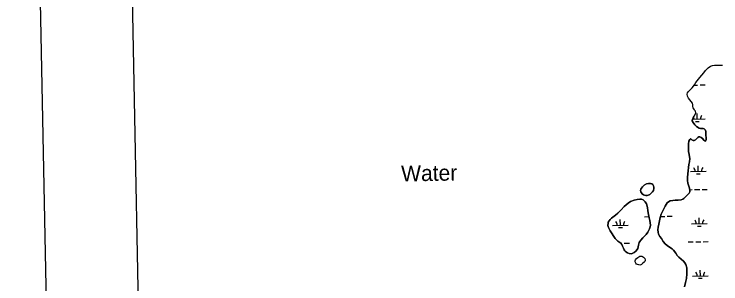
# Model space of a CAD drawing. Extents: x 3989314 to 4027622, y 243956 to 270014.
# Drawn here: x 3992659 to 3997154, y 258022 to 259739 of the extents above; entities that cross this region are included whole.
import ezdxf

# ---------------------------------------------------------------- set-up
doc = ezdxf.new("R2010")
doc.units = 0
for name, color, linetype in [('V-ANNO-SYMB', 7, 'Continuous'), ('V-GRID-FRAM', 7, 'Continuous'), ('V-RIVR-EDGE', 7, 'Continuous'), ('V-RIVR-IDEN', 7, 'Continuous'), ('V-WETL-SWMP', 7, 'Continuous')]:
    doc.layers.add(name, color=color, linetype=linetype)

msp = doc.modelspace()

# ---------------------------------------------------------------- linework, layer by layer
at = {"layer": 'V-ANNO-SYMB'}
msp.add_lwpolyline([(3993116.1, 245218.5), (4026192.7, 245877.7), (4025736.1, 268789.7), (3992659.5, 268130.6), (3993116.1, 245218.5)], dxfattribs=at)
at = {"layer": 'V-GRID-FRAM'}
msp.add_lwpolyline([(3993261.4, 267575.2), (4025156.8, 268210.8), (4025527.1, 250031.9), (3993615.7, 249396), (3993261.4, 267575.2)], dxfattribs=at)
at = {"layer": 'V-RIVR-EDGE'}
for points in [[(3996977.4, 259078.8), (3996984.3, 259088.8), (3996992.4, 259103.6), (3996994.4, 259111), (3996993.6, 259120.5), (3996989.7, 259126.5), (3996985.8, 259130.9), (3996978.6, 259142.5), (3996976.5, 259151.1), (3996975.6, 259161.5), (3996972.9, 259173.2), (3996957.5, 259192.7), (3996948.4, 259204.7), (3996942.3, 259216.8), (3996941, 259229), (3996942.4, 259237.6), (3996945.6, 259244.6), (3996951.7, 259251.7), (3996971, 259269.4), (3996986.1, 259288.9), (3996995.4, 259305), (3997019.8, 259336.4), (3997046.6, 259365.6), (3997057.4, 259380.3), (3997073.8, 259397.6), (3997087.9, 259407), (3997100.3, 259412), (3997114.6, 259414.7), (3997134, 259414.8), (3997150.8, 259413.4), (3997163.9, 259414.5)], [(3996977.4, 259078.8), (3996974, 259070.4), (3996972.8, 259060), (3996977.1, 259049.6), (3996989.2, 259033.9), (3996999.9, 259023.5), (3997016.9, 259013.4), (3997024.5, 259011.2), (3997033.7, 259010.6), (3997042.3, 259010.6), (3997048.4, 259008.6), (3997055.8, 259000.7), (3997058.9, 258989.7), (3997059.2, 258971.9), (3997060.1, 258947), (3997059.8, 258938.6), (3997057.9, 258933.7), (3997055.7, 258931.2), (3997052.8, 258931.6), (3997045.3, 258936.3), (3997036.8, 258947.1), (3997029.2, 258954.6), (3997021.1, 258958.7), (3997014.5, 258958.6), (3997008.4, 258953.7), (3997001.9, 258946.9), (3996992.7, 258937.9), (3996984.2, 258934), (3996977.6, 258934.6), (3996970.5, 258938.8), (3996963.3, 258944.9), (3996961, 258944.5), (3996957.2, 258941.4), (3996951.3, 258930.1), (3996949.1, 258913.4), (3996948.2, 258882.1), (3996948.5, 258865.6), (3996952.3, 258846), (3996955.6, 258831.5), (3996956.3, 258819.2), (3996954.5, 258799.4), (3996951.2, 258780.8), (3996943.2, 258721.9), (3996941.1, 258699.8), (3996941.6, 258681), (3996944.9, 258662.1), (3996950.7, 258643.7), (3996954.5, 258632.1), (3996957, 258616.6), (3996956.2, 258608.4), (3996952, 258599.6), (3996946.3, 258593), (3996935.7, 258583), (3996927.8, 258574.9), (3996919, 258566.3), (3996911.7, 258561.6), (3996901.3, 258557.5), (3996883.3, 258555.1), (3996862.9, 258554.6), (3996847.8, 258553.3), (3996831.6, 258550.2), (3996822.3, 258545.1), (3996813.3, 258537.5), (3996799.7, 258515.9), (3996787.6, 258491.6), (3996775.4, 258465.4), (3996769, 258445.1), (3996759, 258402.8), (3996754.9, 258383.6), (3996753.4, 258366.6), (3996754.7, 258350.9), (3996758.6, 258338), (3996765.4, 258323.9), (3996775.7, 258309.7), (3996788.3, 258291.8), (3996799.4, 258277.7), (3996813.3, 258266.3), (3996826.6, 258256.2), (3996843.6, 258244.4), (3996852.5, 258236.7), (3996867.3, 258216.9), (3996876.7, 258202.3), (3996887.8, 258191.1), (3996901.9, 258179.3), (3996917.3, 258165.7), (3996925.3, 258156.7), (3996930.9, 258145.3), (3996937.1, 258123.1), (3996938.3, 258102.6), (3996937.7, 258084.8), (3996935, 258056.8), (3996929.2, 258030.9), (3996922.8, 258003.7)], [(3996645.4, 258607.6), (3996649.1, 258600.9), (3996654.4, 258594.1), (3996662, 258589.1), (3996668.9, 258586.7), (3996677.1, 258585.1), (3996686.2, 258585.1), (3996692.6, 258586.6), (3996698.7, 258589.4), (3996701.9, 258591.5), (3996708.6, 258597.7), (3996719.2, 258608.7), (3996725.1, 258616.9), (3996727.9, 258628.7), (3996728, 258637.1), (3996726.6, 258645.8), (3996721, 258654.4), (3996716.1, 258658.8), (3996707.7, 258661.9), (3996694.7, 258661.6), (3996681.4, 258657.7), (3996667.2, 258649.5), (3996655.6, 258639.2), (3996648.5, 258631.6), (3996644.9, 258624.3), (3996643.3, 258616.9), (3996645.4, 258607.6)], [(3996439.2, 258381.1), (3996450.3, 258360), (3996462.5, 258339.9), (3996468.6, 258329.5), (3996481.8, 258310.2), (3996494, 258297), (3996498.7, 258294), (3996506.3, 258289.9), (3996512.5, 258285.7), (3996517.6, 258281.2), (3996523.5, 258273.1), (3996528.5, 258262.7), (3996534.4, 258248.2), (3996538.6, 258238.7), (3996544.5, 258231.6), (3996550.2, 258226.3), (3996559.6, 258220), (3996570.1, 258214.8), (3996582.9, 258213.6), (3996591.1, 258215.5), (3996602.2, 258221.4), (3996613.6, 258230.4), (3996622.5, 258239.9), (3996626.4, 258247.6), (3996629.8, 258267.2), (3996631.6, 258276.4), (3996634.8, 258284.8), (3996638.8, 258291.3), (3996645.5, 258300.9), (3996657.3, 258315.3), (3996665.8, 258323.2), (3996678.6, 258337), (3996689.7, 258351.5), (3996699.6, 258371.5), (3996704.5, 258385.8), (3996706.1, 258396.4), (3996705.2, 258411.5), (3996703.1, 258425.5), (3996699.1, 258442.9), (3996693.7, 258464.4), (3996689.7, 258486.4), (3996686.8, 258508.9), (3996680.6, 258530.7), (3996673, 258543.1), (3996667.4, 258550), (3996659.9, 258556.5), (3996648.6, 258560.3), (3996638.7, 258560.8), (3996622.8, 258559.1), (3996603.4, 258554.4), (3996580.4, 258545.3), (3996564.8, 258536.5), (3996551.1, 258525.8), (3996538.6, 258514.1), (3996521.1, 258494.1), (3996498, 258471.1), (3996484.8, 258460.3), (3996459.8, 258440.4), (3996449.8, 258430.7), (3996444.4, 258423.8), (3996437.7, 258414.6), (3996436.7, 258408.9), (3996435.7, 258393), (3996439.2, 258381.1)], [(3996611.8, 258175.2), (3996617.9, 258182.6), (3996627.1, 258189.9), (3996638.6, 258197.5), (3996644.5, 258198.4), (3996651.7, 258198.2), (3996656.8, 258196.2), (3996662.9, 258191.9), (3996668.2, 258186.4), (3996670.7, 258182.4), (3996673.2, 258175.7), (3996672.8, 258170.2), (3996670.8, 258165.1), (3996665.9, 258159.5), (3996656.2, 258151.1), (3996649.9, 258144.2), (3996645, 258142.7), (3996638.7, 258141.5), (3996631.9, 258142.2), (3996624.4, 258144.9), (3996618.7, 258147.7), (3996613.6, 258153.2), (3996610.3, 258161.1), (3996610, 258168.9), (3996611.8, 258175.2)]]:
    msp.add_lwpolyline(points, dxfattribs=at)
at = {"layer": 'V-WETL-SWMP'}
for p, q in [((3997057.4, 259380.3), (3997073.8, 259397.6)), ((3997073.8, 259397.6), (3997087.9, 259407)), ((3997087.9, 259407), (3997100.3, 259412)), ((3997100.3, 259412), (3997114.6, 259414.7)), ((3997114.6, 259414.7), (3997134, 259414.8)), ((3997134, 259414.8), (3997150.8, 259413.4)), ((3997150.8, 259413.4), (3997163.9, 259414.5)), ((3997019.8, 259336.4), (3997046.6, 259365.6)), ((3997046.6, 259365.6), (3997057.4, 259380.3)), ((3996995.4, 259305), (3997019.8, 259336.4)), ((3996951.7, 259251.7), (3996971, 259269.4)), ((3996971, 259269.4), (3996986.1, 259288.9)), ((3996985.1, 259287.5), (3997006.2, 259288)), ((3996986.1, 259288.9), (3996995.4, 259305)), ((3997022.2, 259288.3), (3997054.2, 259288.9)), ((3996941, 259229), (3996942.4, 259237.6)), ((3996942.3, 259216.8), (3996941, 259229)), ((3996948.4, 259204.7), (3996942.3, 259216.8)), ((3996942.4, 259237.6), (3996945.6, 259244.6)), ((3996945.6, 259244.6), (3996951.7, 259251.7)), ((3996957.5, 259192.7), (3996948.4, 259204.7)), ((3996972.9, 259173.2), (3996957.5, 259192.7)), ((3996975.6, 259161.5), (3996972.9, 259173.2)), ((3996976.5, 259151.1), (3996975.6, 259161.5)), ((3996978.6, 259142.5), (3996976.5, 259151.1)), ((3996985.8, 259130.9), (3996978.6, 259142.5)), ((3996989.7, 259126.5), (3996985.8, 259130.9)), ((3996993.6, 259120.5), (3996989.7, 259126.5)), ((3996977.4, 259078.8), (3996984.3, 259088.8)), ((3996984.3, 259088.8), (3996992.4, 259103.6)), ((3996992.4, 259103.6), (3996994.4, 259111)), ((3996994.4, 259111), (3996993.6, 259120.5)), ((3997004, 259070.6), (3997003.3, 259106.6)), ((3996972.8, 259060), (3996974, 259070.4)), ((3996977.1, 259049.6), (3996972.8, 259060)), ((3996974, 259070.4), (3996977.4, 259078.8)), ((3996974, 259070), (3997054, 259071.6)), ((3996989.2, 259033.9), (3996977.1, 259049.6)), ((3996992.3, 259055), (3997016.3, 259055.4)), ((3996999.9, 259023.5), (3996989.2, 259033.9)), ((3997016.9, 259013.4), (3996999.9, 259023.5)), ((3997024.5, 259011.2), (3997016.9, 259013.4)), ((3997033.7, 259010.6), (3997024.5, 259011.2)), ((3997042.3, 259010.6), (3997033.7, 259010.6)), ((3997048.4, 259008.6), (3997042.3, 259010.6)), ((3997055.8, 259000.7), (3997048.4, 259008.6)), ((3997058.9, 258989.7), (3997055.8, 259000.7)), ((3996992.7, 258937.9), (3997001.9, 258946.9)), ((3997001.9, 258946.9), (3997008.4, 258953.7)), ((3997008.4, 258953.7), (3997014.5, 258958.6)), ((3997010.4, 258955.3), (3997012.9, 258955.4)), ((3997014.5, 258958.6), (3997021.1, 258958.7)), ((3997021.1, 258958.7), (3997029.2, 258954.6)), ((3997029.2, 258954.6), (3997036.8, 258947.1)), ((3997036.8, 258947.1), (3997045.3, 258936.3)), ((3997059.2, 258971.9), (3997058.9, 258989.7)), ((3997060.1, 258947), (3997059.2, 258971.9)), ((3997059.7, 258956.3), (3997060.9, 258956.3)), ((3997059.8, 258938.6), (3997060.1, 258947)), ((3996948.2, 258882.1), (3996949.1, 258913.4)), ((3996949.1, 258913.4), (3996951.3, 258930.1)), ((3996951.3, 258930.1), (3996957.2, 258941.4)), ((3996957.2, 258941.4), (3996961, 258944.5)), ((3996961, 258944.5), (3996963.3, 258944.9)), ((3996963.3, 258944.9), (3996970.5, 258938.8)), ((3996970.5, 258938.8), (3996977.6, 258934.6)), ((3996977.6, 258934.6), (3996984.2, 258934)), ((3996984.2, 258934), (3996992.7, 258937.9)), ((3997045.3, 258936.3), (3997052.8, 258931.6)), ((3997052.8, 258931.6), (3997055.7, 258931.2)), ((3997055.7, 258931.2), (3997057.9, 258933.7)), ((3997057.9, 258933.7), (3997059.8, 258938.6)), ((3996948.5, 258865.6), (3996948.2, 258882.1)), ((3996952.3, 258846), (3996948.5, 258865.6)), ((3996955.6, 258831.5), (3996952.3, 258846)), ((3996954.5, 258799.4), (3996956.3, 258819.2)), ((3996956.3, 258819.2), (3996955.6, 258831.5)), ((3996943.2, 258721.9), (3996951.2, 258780.8)), ((3996951.2, 258780.8), (3996954.5, 258799.4)), ((3997010.6, 258738), (3997009.9, 258774)), ((3996941.1, 258699.8), (3996943.2, 258721.9)), ((3996960.6, 258737), (3997060.6, 258739)), ((3996998.9, 258722.4), (3997022.9, 258722.8)), ((3996941.6, 258681), (3996941.1, 258699.8)), ((3996944.9, 258662.1), (3996941.6, 258681)), ((3996950.7, 258643.7), (3996944.9, 258662.1)), ((3996954.5, 258632.1), (3996950.7, 258643.7)), ((3996957, 258616.6), (3996954.5, 258632.1)), ((3996935.7, 258583), (3996946.3, 258593)), ((3996946.3, 258593), (3996952, 258599.6)), ((3996952, 258599.6), (3996956.2, 258608.4)), ((3996956.2, 258621.5), (3996971.5, 258621.8)), ((3996956.2, 258608.4), (3996957, 258616.6)), ((3996987.5, 258622.1), (3997019.5, 258622.7)), ((3997035.5, 258623.1), (3997067.5, 258623.7)), ((3996813.3, 258537.5), (3996822.3, 258545.1)), ((3996822.3, 258545.1), (3996831.6, 258550.2)), ((3996831.6, 258550.2), (3996847.8, 258553.3)), ((3996847.8, 258553.3), (3996862.9, 258554.6)), ((3996862.9, 258554.6), (3996883.3, 258555.1)), ((3996883.3, 258555.1), (3996901.3, 258557.5)), ((3996901.3, 258557.5), (3996911.7, 258561.6)), ((3996911.7, 258561.6), (3996919, 258566.3)), ((3996919, 258566.3), (3996927.8, 258574.9)), ((3996927.8, 258574.9), (3996935.7, 258583)), ((3996787.6, 258491.6), (3996799.7, 258515.9)), ((3996799.7, 258515.9), (3996813.3, 258537.5)), ((3996769, 258445.1), (3996775.4, 258465.4)), ((3996775.4, 258465.4), (3996787.6, 258491.6)), ((3996813, 258452.1), (3996844.9, 258452.7)), ((3996515.4, 258395.4), (3996514.7, 258431.4)), ((3996669, 258449.2), (3996697.4, 258449.8)), ((3996759, 258402.8), (3996769, 258445.1)), ((3996770.9, 258451.3), (3996797, 258451.8)), ((3997017.2, 258405.4), (3997016.5, 258441.4)), ((3996465.4, 258394.4), (3996565.4, 258396.4)), ((3996503.7, 258379.7), (3996527.7, 258380.2)), ((3996753.4, 258366.6), (3996754.9, 258383.6)), ((3996754.7, 258350.9), (3996753.4, 258366.6)), ((3996754.9, 258383.6), (3996759, 258402.8)), ((3996967.3, 258404.4), (3997067.2, 258406.4)), ((3997005.6, 258389.7), (3997029.5, 258390.2)), ((3996758.6, 258338), (3996754.7, 258350.9)), ((3996765.4, 258323.9), (3996758.6, 258338)), ((3996775.7, 258309.7), (3996765.4, 258323.9)), ((3996518.5, 258280), (3996524.3, 258280.1)), ((3996540.3, 258280.5), (3996572.3, 258281.1)), ((3996788.3, 258291.8), (3996775.7, 258309.7)), ((3996799.4, 258277.7), (3996788.3, 258291.8)), ((3996813.3, 258266.3), (3996799.4, 258277.7)), ((3996946.1, 258288.5), (3996978.1, 258289.2)), ((3996994.1, 258289.5), (3997026.1, 258290.1)), ((3997042.1, 258290.5), (3997074.1, 258291.1)), ((3996826.6, 258256.2), (3996813.3, 258266.3)), ((3996843.6, 258244.4), (3996826.6, 258256.2)), ((3996852.5, 258236.7), (3996843.6, 258244.4)), ((3996867.3, 258216.9), (3996852.5, 258236.7)), ((3996876.7, 258202.3), (3996867.3, 258216.9)), ((3996887.8, 258191.1), (3996876.7, 258202.3)), ((3996901.9, 258179.3), (3996887.8, 258191.1)), ((3996917.3, 258165.7), (3996901.9, 258179.3)), ((3996925.3, 258156.7), (3996917.3, 258165.7)), ((3996930.9, 258145.3), (3996925.3, 258156.7)), ((3996937.1, 258123.1), (3996930.9, 258145.3)), ((3996938.3, 258102.6), (3996937.1, 258123.1)), ((3996937.7, 258084.8), (3996938.3, 258102.6)), ((3997023.9, 258072.8), (3997023.2, 258108.8)), ((3996929.2, 258030.9), (3996935, 258056.8)), ((3996935, 258056.8), (3996937.7, 258084.8)), ((3996973.9, 258071.8), (3997073.9, 258073.8)), ((3997012.2, 258057.1), (3997036.2, 258057.6)), ((3996922.8, 258003.7), (3996929.2, 258030.9))]:
    msp.add_line(p, q, dxfattribs=at)
for points in [[(3996649.1, 258600.9), (3996645.4, 258607.6), (3996643.3, 258616.9), (3996644.9, 258624.3), (3996648.5, 258631.6), (3996655.6, 258639.2), (3996667.2, 258649.5), (3996681.4, 258657.7), (3996694.7, 258661.6), (3996707.7, 258661.9), (3996716.1, 258658.8), (3996721, 258654.4), (3996726.6, 258645.8), (3996728, 258637.1), (3996727.9, 258628.7), (3996725.1, 258616.9), (3996719.2, 258608.7), (3996708.6, 258597.7), (3996701.9, 258591.5), (3996698.7, 258589.4), (3996692.6, 258586.6), (3996686.2, 258585.1), (3996677.1, 258585.1), (3996668.9, 258586.7), (3996662, 258589.1), (3996654.4, 258594.1)], [(3996450.3, 258360), (3996439.2, 258381.1), (3996435.7, 258393), (3996436.7, 258408.9), (3996437.7, 258414.6), (3996444.4, 258423.8), (3996449.8, 258430.7), (3996459.8, 258440.4), (3996484.8, 258460.3), (3996498, 258471.1), (3996521.1, 258494.1), (3996538.6, 258514.1), (3996551.1, 258525.8), (3996564.8, 258536.5), (3996580.4, 258545.3), (3996603.4, 258554.4), (3996622.8, 258559.1), (3996638.7, 258560.8), (3996648.6, 258560.3), (3996659.9, 258556.5), (3996667.4, 258550), (3996673, 258543.1), (3996680.6, 258530.7), (3996686.8, 258508.9), (3996689.7, 258486.4), (3996693.7, 258464.4), (3996699.1, 258442.9), (3996703.1, 258425.5), (3996705.2, 258411.5), (3996706.1, 258396.4), (3996704.5, 258385.8), (3996699.6, 258371.5), (3996689.7, 258351.5), (3996678.6, 258337), (3996665.8, 258323.2), (3996657.3, 258315.3), (3996645.5, 258300.9), (3996638.8, 258291.3), (3996634.8, 258284.8), (3996631.6, 258276.4), (3996629.8, 258267.2), (3996626.4, 258247.6), (3996622.5, 258239.9), (3996613.6, 258230.4), (3996602.2, 258221.4), (3996591.1, 258215.5), (3996582.9, 258213.6), (3996570.1, 258214.8), (3996559.6, 258220), (3996550.2, 258226.3), (3996544.5, 258231.6), (3996538.6, 258238.7), (3996534.4, 258248.2), (3996528.5, 258262.7), (3996523.5, 258273.1), (3996517.6, 258281.2), (3996512.5, 258285.7), (3996506.3, 258289.9), (3996498.6, 258294), (3996494, 258297), (3996481.8, 258310.2), (3996468.6, 258329.5), (3996462.5, 258339.9)], [(3996610, 258168.9), (3996611.8, 258175.2), (3996617.9, 258182.6), (3996627.1, 258189.9), (3996638.6, 258197.5), (3996644.5, 258198.4), (3996651.7, 258198.2), (3996656.8, 258196.2), (3996662.9, 258191.9), (3996668.2, 258186.4), (3996670.7, 258182.4), (3996673.2, 258175.7), (3996672.8, 258170.2), (3996670.8, 258165.1), (3996665.9, 258159.5), (3996656.2, 258151.1), (3996649.9, 258144.2), (3996645, 258142.7), (3996638.7, 258141.5), (3996631.9, 258142.2), (3996624.4, 258144.9), (3996618.7, 258147.7), (3996613.6, 258153.2), (3996610.3, 258161.1)]]:
    msp.add_lwpolyline(points, close=True, dxfattribs=at)
for centre, start, end in [((3996948.7, 259070), 0.3699, 23.542), ((3997059.2, 259072.2), 140.3699, 181.9135), ((3996955.4, 258737.4), 0.3699, 41.9135), ((3997065.8, 258739.6), 140.3699, 181.9135), ((3996460.2, 258394.8), 0.3699, 41.9135), ((3996570.7, 258397), 140.3699, 181.9135), ((3996962, 258404.8), 0.3699, 41.9135), ((3997072.5, 258407), 140.3699, 181.9135), ((3996968.6, 258072.2), 0.3699, 41.9135), ((3997079.1, 258074.4), 140.3699, 181.9135)]:
    msp.add_arc(centre, 35.2, start, end, dxfattribs=at)

# ---------------------------------------------------------------- texts
at = {"layer": 'V-RIVR-IDEN'}
msp.add_text('Water', height=100, rotation=1.0724, dxfattribs=at).set_placement((3995122, 258673.6))

doc.saveas('drawing.dxf')
